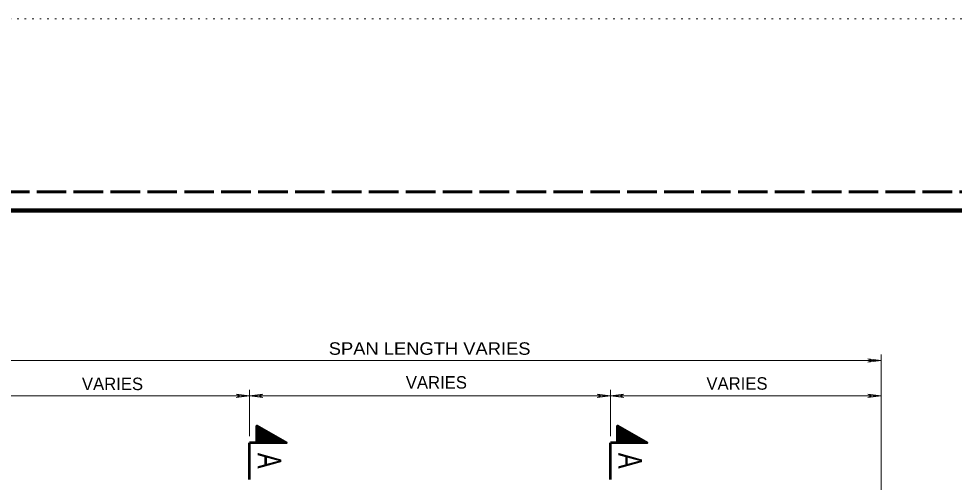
# Model space of a CAD drawing. Extents: x 312583 to 312854, y 144419 to 144597.
# Drawn here: x 312707.1 to 312764.1, y 144568.5 to 144596.8 of the extents above; entities that cross this region are included whole.
import ezdxf
from ezdxf.enums import TextEntityAlignment as Align

# ---------------------------------------------------------------- set-up
doc = ezdxf.new("R2010")
doc.units = 0
doc.header["$LTSCALE"] = 0.3
doc.linetypes.add('DOTTED', pattern=[1.5, 0.3, -1.2])
doc.linetypes.add('LONG_DASHED', pattern=[7.5, 6, -1.5])
doc.layers.add('1', color=7, linetype='Continuous', lineweight=13)
doc.layers.add('63', color=7, linetype='DOTTED', lineweight=13)

msp = doc.modelspace()

# ---------------------------------------------------------------- linework, layer by layer
at = {"layer": '1', "linetype": 'LONG_DASHED', "lineweight": 60}
msp.add_line((312851.75, 144586.2246), (312583.526, 144586.2246), dxfattribs=at)
at = {"layer": '1', "lineweight": 158}
msp.add_line((312616.5, 144585.0846), (312849, 144585.0846), dxfattribs=at)
at = {"layer": '1'}
for p, q in [((312759.6679, 144568.0337), (312759.6679, 144576.2983)), ((312704.6826, 144575.938), (312732.1753, 144575.938)), ((312759.6679, 144575.938), (312732.1753, 144575.938)), ((312758.8553, 144576.0453), (312759.1159, 144575.938)), ((312759.6679, 144575.938), (312758.8553, 144576.0453)), ((312758.8553, 144575.8383), (312759.1159, 144575.938)), ((312759.6679, 144575.938), (312758.8553, 144575.8383)), ((312721.1736, 144571.3227), (312721.1736, 144574.144)), ((312743.1693, 144571.3227), (312743.1693, 144574.144)), ((312704.6826, 144573.7837), (312721.1736, 144573.7837)), ((312720.3609, 144573.8833), (312720.6216, 144573.7837)), ((312721.1736, 144573.7837), (312720.3609, 144573.8833)), ((312720.3609, 144573.684), (312720.6216, 144573.7837)), ((312721.1736, 144573.7837), (312720.3609, 144573.684)), ((312721.1736, 144573.7837), (312721.9863, 144573.8833)), ((312721.1736, 144573.7837), (312732.1753, 144573.7837)), ((312721.1736, 144573.7837), (312721.9863, 144573.684)), ((312721.9863, 144573.8833), (312721.7333, 144573.7837)), ((312721.9863, 144573.684), (312721.7333, 144573.7837)), ((312743.1693, 144573.7837), (312732.1753, 144573.7837)), ((312742.3566, 144573.8833), (312742.6173, 144573.7837)), ((312743.1693, 144573.7837), (312742.3566, 144573.8833)), ((312742.3566, 144573.684), (312742.6173, 144573.7837)), ((312743.1693, 144573.7837), (312742.3566, 144573.684)), ((312743.1693, 144573.7837), (312743.9819, 144573.8833)), ((312759.6679, 144573.7837), (312743.1693, 144573.7837)), ((312743.1693, 144573.7837), (312743.9819, 144573.684)), ((312743.9819, 144573.8833), (312743.7213, 144573.7837)), ((312743.9819, 144573.684), (312743.7213, 144573.7837)), ((312758.8553, 144573.8833), (312759.1159, 144573.7837)), ((312759.6679, 144573.7837), (312758.8553, 144573.8833)), ((312758.8553, 144573.684), (312759.1159, 144573.7837)), ((312759.6679, 144573.7837), (312758.8553, 144573.684))]:
    msp.add_line(p, q, dxfattribs=at)
at = {"layer": '1', "lineweight": 35}
for p, q in [((312721.6259, 144571.9283), (312721.6336, 144571.9437)), ((312721.6259, 144571.89), (312721.6566, 144571.936)), ((312721.6259, 144571.8363), (312721.6719, 144571.9207)), ((312721.6259, 144571.798), (312721.6949, 144571.913)), ((312721.6259, 144571.7443), (312721.7179, 144571.9053)), ((312721.6259, 144571.706), (312721.7333, 144571.89)), ((312721.6259, 144571.66), (312721.7486, 144571.8823)), ((312721.6259, 144571.614), (312721.7716, 144571.867)), ((312721.6259, 144571.568), (312721.7869, 144571.8593)), ((312721.6259, 144571.5297), (312721.8176, 144571.844)), ((312721.6259, 144571.476), (312721.8329, 144571.8363)), ((312721.6259, 144571.4377), (312721.8559, 144571.821)), ((312721.6259, 144571.3917), (312721.8713, 144571.8133)), ((312721.6259, 144571.338), (312721.8866, 144571.798)), ((312721.6259, 144571.2997), (312721.9096, 144571.798)), ((312721.6259, 144571.2537), (312721.9249, 144571.7827)), ((312721.6259, 144571.2077), (312721.9479, 144571.7673)), ((312721.6259, 144571.1617), (312721.9709, 144571.7597)), ((312721.6259, 144571.1157), (312721.9786, 144571.7443)), ((312721.6259, 144571.0773), (312722.0016, 144571.729)), ((312743.6139, 144571.9283), (312743.6293, 144571.9437)), ((312743.6139, 144571.89), (312743.6523, 144571.936)), ((312743.6139, 144571.8363), (312743.6676, 144571.9207)), ((312743.6139, 144571.798), (312743.6906, 144571.913)), ((312743.6139, 144571.7443), (312743.7059, 144571.9053)), ((312743.6139, 144571.706), (312743.7213, 144571.89)), ((312743.6139, 144571.66), (312743.7443, 144571.8823)), ((312743.6139, 144571.614), (312743.7673, 144571.867)), ((312743.6139, 144571.568), (312743.7826, 144571.8593)), ((312743.6139, 144571.5297), (312743.8133, 144571.844)), ((312743.6139, 144571.476), (312743.8209, 144571.8363)), ((312743.6139, 144571.4377), (312743.8439, 144571.821)), ((312743.6139, 144571.3917), (312743.8669, 144571.8133)), ((312743.6139, 144571.338), (312743.8823, 144571.798)), ((312743.6139, 144571.2997), (312743.9053, 144571.798)), ((312743.6139, 144571.2537), (312743.9206, 144571.7827)), ((312743.6139, 144571.2077), (312743.9359, 144571.7673)), ((312743.6139, 144571.1617), (312743.9589, 144571.7597)), ((312743.6139, 144571.1157), (312743.9743, 144571.7443)), ((312743.6139, 144571.0773), (312743.9973, 144571.729)), ((312721.6259, 144571.0237), (312722.0246, 144571.7213)), ((312721.6259, 144570.993), (312722.0399, 144571.706)), ((312721.6259, 144570.9393), (312722.0706, 144571.6983)), ((312721.6336, 144570.9163), (312722.0859, 144571.683)), ((312721.6643, 144570.9163), (312722.1013, 144571.683)), ((312721.6949, 144570.9163), (312722.1243, 144571.6677)), ((312721.7179, 144570.9163), (312722.1396, 144571.66)), ((312721.7409, 144570.9163), (312722.1626, 144571.6447)), ((312721.7639, 144570.924), (312722.1856, 144571.637)), ((312721.7946, 144570.924), (312722.2009, 144571.6217)), ((312721.8176, 144570.9163), (312722.2163, 144571.614)), ((312721.8483, 144570.9163), (312722.2393, 144571.5987)), ((312721.8713, 144570.9163), (312722.2546, 144571.5833)), ((312721.8943, 144570.9163), (312722.2776, 144571.5757)), ((312721.9249, 144570.9163), (312722.3006, 144571.568)), ((312721.9556, 144570.9163), (312722.3159, 144571.5527)), ((312721.9709, 144570.9163), (312722.3313, 144571.545)), ((312722.0016, 144570.924), (312722.3543, 144571.5297)), ((312722.0323, 144570.9163), (312722.3773, 144571.522)), ((312722.0553, 144570.9163), (312722.3926, 144571.5067)), ((312722.0783, 144570.9163), (312722.4156, 144571.499)), ((312722.1013, 144570.9163), (312722.4309, 144571.4837)), ((312722.1319, 144570.9163), (312722.4463, 144571.476)), ((312722.1626, 144570.9163), (312722.4693, 144571.4607)), ((312722.1856, 144570.9163), (312722.4923, 144571.453)), ((312722.2086, 144570.9163), (312722.5076, 144571.4453)), ((312722.2316, 144570.924), (312722.5383, 144571.4377)), ((312722.2623, 144570.9163), (312722.5459, 144571.4223)), ((312722.2853, 144570.9163), (312722.5689, 144571.407)), ((312722.3159, 144570.9163), (312722.5919, 144571.3993)), ((312722.3389, 144570.9163), (312722.6073, 144571.384)), ((312722.3619, 144570.9163), (312722.6303, 144571.3763)), ((312722.3926, 144570.9163), (312722.6533, 144571.361)), ((312722.4233, 144570.9163), (312722.6609, 144571.3533)), ((312722.4386, 144570.9163), (312722.6839, 144571.338)), ((312722.4693, 144570.9163), (312722.7069, 144571.338)), ((312722.4999, 144570.9163), (312722.7223, 144571.3227)), ((312722.5229, 144570.9163), (312722.7453, 144571.315)), ((312722.5459, 144570.9163), (312722.7683, 144571.2997)), ((312722.5689, 144570.9163), (312722.7836, 144571.292)), ((312722.5996, 144570.9163), (312722.7989, 144571.2767)), ((312722.6303, 144570.9163), (312722.8219, 144571.2613)), ((312722.6533, 144570.9163), (312722.8449, 144571.2537)), ((312722.6763, 144570.9163), (312722.8603, 144571.2383)), ((312722.6993, 144570.9163), (312722.8833, 144571.223)), ((312722.7299, 144570.9163), (312722.8986, 144571.223)), ((312722.7529, 144570.9163), (312722.9139, 144571.2077)), ((312722.7759, 144570.9163), (312722.9369, 144571.2)), ((312722.8066, 144570.9163), (312722.9599, 144571.1847)), ((312722.8296, 144570.9163), (312722.9753, 144571.177)), ((312722.8603, 144570.9163), (312723.0059, 144571.1617)), ((312743.6139, 144571.0237), (312744.0203, 144571.7213)), ((312743.6139, 144570.993), (312744.0356, 144571.706)), ((312743.6139, 144570.9393), (312744.0586, 144571.6983)), ((312743.6293, 144570.9163), (312744.0739, 144571.683)), ((312743.6599, 144570.9163), (312744.0969, 144571.683)), ((312743.6906, 144570.9163), (312744.1199, 144571.6677)), ((312743.7059, 144570.9163), (312744.1353, 144571.66)), ((312743.7366, 144570.9163), (312744.1583, 144571.6447)), ((312743.7596, 144570.924), (312744.1736, 144571.637)), ((312743.7903, 144570.924), (312744.1889, 144571.6217)), ((312743.8133, 144570.9163), (312744.2119, 144571.614)), ((312743.8363, 144570.9163), (312744.2349, 144571.5987)), ((312743.8669, 144570.9163), (312744.2503, 144571.5833)), ((312743.8899, 144570.9163), (312744.2733, 144571.5757)), ((312743.9206, 144570.9163), (312744.2886, 144571.568)), ((312743.9436, 144570.9163), (312744.3116, 144571.5527)), ((312743.9666, 144570.9163), (312744.3269, 144571.545)), ((312743.9973, 144570.924), (312744.3499, 144571.5297)), ((312744.0279, 144570.9163), (312744.3729, 144571.522)), ((312744.0509, 144570.9163), (312744.3883, 144571.5067)), ((312744.0663, 144570.9163), (312744.4036, 144571.499)), ((312744.0969, 144570.9163), (312744.4266, 144571.4837)), ((312744.1276, 144570.9163), (312744.4419, 144571.476)), ((312744.1583, 144570.9163), (312744.4649, 144571.4607)), ((312744.1736, 144570.9163), (312744.4879, 144571.453)), ((312744.2043, 144570.9163), (312744.5033, 144571.4453)), ((312744.2273, 144570.924), (312744.5263, 144571.4377)), ((312744.2579, 144570.9163), (312744.5416, 144571.4223)), ((312744.2809, 144570.9163), (312744.5646, 144571.407)), ((312744.3039, 144570.9163), (312744.5876, 144571.3993)), ((312744.3346, 144570.9163), (312744.6029, 144571.384)), ((312744.3576, 144570.9163), (312744.6259, 144571.3763)), ((312744.3883, 144570.9163), (312744.6413, 144571.361)), ((312744.4113, 144570.9163), (312744.6566, 144571.3533)), ((312744.4343, 144570.9163), (312744.6796, 144571.338)), ((312744.4649, 144570.9163), (312744.7026, 144571.338)), ((312744.4956, 144570.9163), (312744.7179, 144571.3227)), ((312744.5109, 144570.9163), (312744.7409, 144571.315)), ((312744.5339, 144570.9163), (312744.7563, 144571.2997)), ((312744.5646, 144570.9163), (312744.7793, 144571.292)), ((312744.5953, 144570.9163), (312744.7946, 144571.2767)), ((312744.6259, 144570.9163), (312744.8176, 144571.2613)), ((312744.6413, 144570.9163), (312744.8406, 144571.2537)), ((312744.6719, 144570.9163), (312744.8559, 144571.2383)), ((312744.6949, 144570.9163), (312744.8713, 144571.223)), ((312744.7256, 144570.9163), (312744.8943, 144571.223)), ((312744.7409, 144570.9163), (312744.9096, 144571.2077)), ((312744.7716, 144570.9163), (312744.9326, 144571.2)), ((312744.8023, 144570.9163), (312744.9556, 144571.1847)), ((312744.8253, 144570.9163), (312744.9709, 144571.177)), ((312744.8559, 144570.9163), (312744.9939, 144571.1617)), ((312722.8833, 144570.9163), (312723.0136, 144571.154)), ((312722.9063, 144570.9163), (312723.0366, 144571.1387)), ((312722.9369, 144570.9163), (312723.0596, 144571.131)), ((312722.9599, 144570.9163), (312723.0749, 144571.1157)), ((312722.9906, 144570.9163), (312723.0979, 144571.108)), ((312723.0059, 144570.9163), (312723.1209, 144571.1003)), ((312723.0366, 144570.9163), (312723.1286, 144571.085)), ((312723.0673, 144570.9163), (312723.1516, 144571.0773)), ((312723.0979, 144570.9163), (312723.1746, 144571.062)), ((312723.1209, 144570.9163), (312723.1899, 144571.0467)), ((312723.1439, 144570.9163), (312723.2129, 144571.039)), ((312723.1669, 144570.9163), (312723.2359, 144571.0237)), ((312723.1899, 144570.9163), (312723.2513, 144571.016)), ((312723.2206, 144570.9163), (312723.2666, 144571.0007)), ((312723.2436, 144570.9163), (312723.2896, 144570.993)), ((312723.2743, 144570.9163), (312723.3126, 144570.9853)), ((312723.2973, 144570.9163), (312723.3279, 144570.9777)), ((312723.3279, 144570.9163), (312723.3509, 144570.9623)), ((312723.3509, 144570.9163), (312723.3663, 144570.9547)), ((312723.3739, 144570.9163), (312723.3816, 144570.9393)), ((312723.4046, 144570.9163), (312723.4046, 144570.9317)), ((312744.8713, 144570.9163), (312745.0093, 144571.154)), ((312744.9019, 144570.9163), (312745.0323, 144571.1387)), ((312744.9326, 144570.9163), (312745.0553, 144571.131)), ((312744.9556, 144570.9163), (312745.0706, 144571.1157)), ((312744.9786, 144570.9163), (312745.0859, 144571.108)), ((312745.0016, 144570.9163), (312745.1089, 144571.1003)), ((312745.0323, 144570.9163), (312745.1243, 144571.085)), ((312745.0629, 144570.9163), (312745.1473, 144571.0773)), ((312745.0859, 144570.9163), (312745.1703, 144571.062)), ((312745.1089, 144570.9163), (312745.1856, 144571.0467)), ((312745.1396, 144570.9163), (312745.2009, 144571.039)), ((312745.1626, 144570.9163), (312745.2239, 144571.0237)), ((312745.1856, 144570.9163), (312745.2469, 144571.016)), ((312745.2086, 144570.9163), (312745.2623, 144571.0007)), ((312745.2393, 144570.9163), (312745.2853, 144570.993)), ((312745.2699, 144570.9163), (312745.3083, 144570.9853)), ((312745.2929, 144570.9163), (312745.3159, 144570.9777)), ((312745.3159, 144570.9163), (312745.3389, 144570.9623)), ((312745.3389, 144570.9163), (312745.3619, 144570.9547)), ((312745.3696, 144570.9163), (312745.3773, 144570.9393)), ((312745.4003, 144570.9163), (312745.4003, 144570.9317))]:
    msp.add_line(p, q, dxfattribs=at)
at = {"layer": '1', "lineweight": 53}
for p, q in [((312721.1736, 144568.6777), (312721.1736, 144570.9163)), ((312721.6259, 144570.9163), (312721.1736, 144570.9163)), ((312743.1693, 144568.6777), (312743.1693, 144570.9163)), ((312743.6139, 144570.9163), (312743.1693, 144570.9163))]:
    msp.add_line(p, q, dxfattribs=at)
for points in [[(312721.6259, 144570.9163), (312721.6259, 144571.959), (312723.4199, 144570.9163)], [(312743.6139, 144570.9163), (312743.6139, 144571.959), (312745.4156, 144570.9163)]]:
    msp.add_lwpolyline(points, close=True, dxfattribs=at)
at = {"layer": '63'}
msp.add_line((312601.2, 144596.7846), (312853.5, 144596.7846), dxfattribs=at)

# ---------------------------------------------------------------- texts
at = {"layer": '1', "width": 1.1}
msp.add_text('SPAN LENGTH VARIES', height=0.76, dxfattribs=at).set_placement((312726.0018, 144576.2861))
at = {"layer": '1'}
for p in [(312710.9554, 144574.1324), (312730.6988, 144574.2235), (312749.0242, 144574.1563)]:
    msp.add_text('VARIES', height=0.76, dxfattribs=at).set_placement(p)
at = {"layer": '1', "width": 0.75}
for p in [(312721.6643, 144569.8238), (312743.6599, 144569.8238)]:
    msp.add_text('A', height=1.437, rotation=270, dxfattribs=at).set_placement(p, align=Align.CENTER)

doc.saveas('drawing.dxf')
